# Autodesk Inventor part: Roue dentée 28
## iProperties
Created: 2002-05
Part Number: Roue dentée 28
Material: Par défaut
Document SubType Name: Modélisation
Designer: Flavien MARTY
Control State: 0
Master: False
Checked Out: False
Shininess: 20.0
Length Units: 11269
Angle Units: 11279
Time Units: 11290
Mass Units: 11283
Length Display Precision: 3
Angle Display Precision: 2
Compacted: True
Density: 0.0
Volumn: 0.0
Area: 0.0
PropertySet Name: Model Information
Author: Flavien MARTY
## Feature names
1. Extrusion1
2. Extrusion2
3. Perçage1 [Hole]
4. Extrusion3
